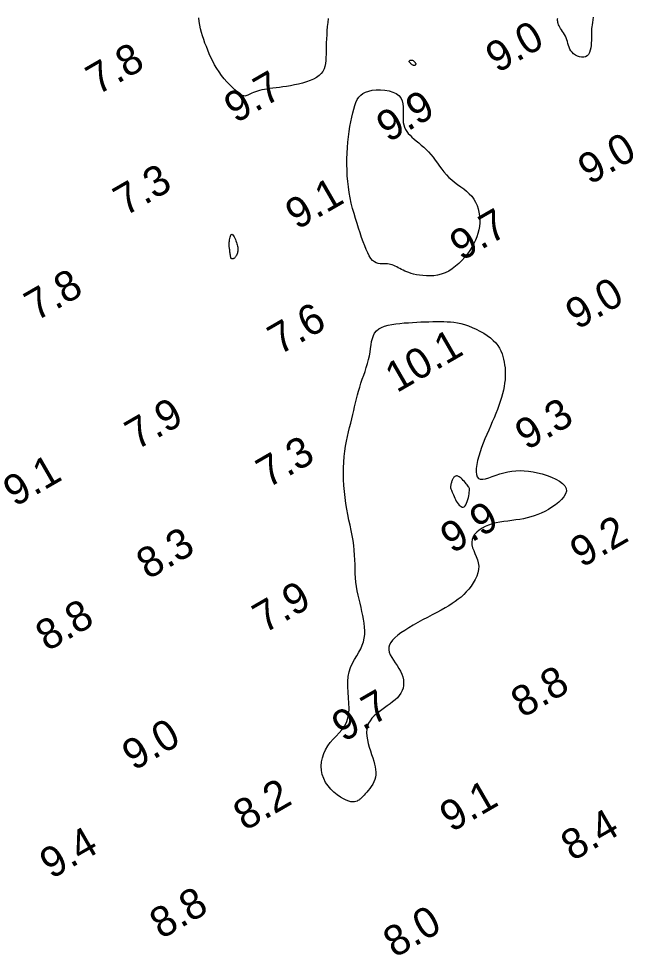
# Model space of a CAD drawing. Extents: x 3024098 to 3056816, y 418252 to 509144.
# Drawn here: x 3036798.1 to 3036899.4, y 419407 to 419561.2 of the extents above; entities that cross this region are included whole.
import ezdxf

# ---------------------------------------------------------------- set-up
doc = ezdxf.new("R2010")
doc.units = 0
doc.layers.add('V-CHAN-CONT-EL10', color=7, linetype='Continuous')
doc.layers.add('V-TOPO-SOUN-0911', color=7, linetype='Continuous')

msp = doc.modelspace()

# ---------------------------------------------------------------- linework, layer by layer
at = {"layer": 'V-CHAN-CONT-EL10'}
for points in [[(3036849.14, 419561.3), (3036849.05, 419560.63), (3036848.98, 419559.95), (3036848.92, 419559.27), (3036848.88, 419558.6), (3036848.84, 419557.93), (3036848.82, 419557.27), (3036848.8, 419556.64), (3036848.78, 419556.02), (3036848.77, 419555.43), (3036848.75, 419554.88), (3036848.72, 419554.35), (3036848.67, 419553.86), (3036848.58, 419553.4), (3036848.44, 419552.97), (3036848.25, 419552.57), (3036847.99, 419552.2), (3036847.65, 419551.87), (3036847.22, 419551.57), (3036846.71, 419551.29), (3036846.15, 419551.05), (3036845.54, 419550.83), (3036844.89, 419550.64), (3036844.23, 419550.47), (3036843.56, 419550.33), (3036842.91, 419550.21), (3036842.28, 419550.1), (3036841.67, 419550.02), (3036841.1, 419549.94), (3036840.55, 419549.87), (3036840.02, 419549.81), (3036839.53, 419549.74), (3036839.06, 419549.67), (3036838.62, 419549.6), (3036838.21, 419549.51), (3036837.82, 419549.41), (3036837.46, 419549.3), (3036837.14, 419549.19), (3036836.83, 419549.08), (3036836.56, 419548.97), (3036836.31, 419548.86), (3036836.1, 419548.75), (3036835.91, 419548.66), (3036835.74, 419548.58), (3036835.58, 419548.53), (3036835.41, 419548.5), (3036835.23, 419548.52), (3036835.02, 419548.6), (3036834.78, 419548.72), (3036834.49, 419548.92), (3036834.15, 419549.18), (3036833.76, 419549.52), (3036833.35, 419549.91), (3036832.9, 419550.36), (3036832.45, 419550.84), (3036832, 419551.36), (3036831.56, 419551.91), (3036831.15, 419552.48), (3036830.77, 419553.07), (3036830.42, 419553.66), (3036830.1, 419554.25), (3036829.81, 419554.85), (3036829.54, 419555.46), (3036829.29, 419556.06), (3036829.06, 419556.65), (3036828.83, 419557.24), (3036828.62, 419557.83), (3036828.43, 419558.4), (3036828.25, 419558.98), (3036828.09, 419559.56), (3036827.96, 419560.16), (3036827.86, 419560.76), (3036827.8, 419561.38)], [(3036892.8, 419561.49), (3036892.72, 419561.05), (3036892.65, 419560.63), (3036892.6, 419560.24), (3036892.55, 419559.91), (3036892.53, 419559.62), (3036892.51, 419559.36), (3036892.5, 419559.11), (3036892.5, 419558.87), (3036892.5, 419558.62), (3036892.5, 419558.34), (3036892.5, 419558.02), (3036892.5, 419557.66), (3036892.48, 419557.26), (3036892.44, 419556.85), (3036892.38, 419556.43), (3036892.3, 419556.04), (3036892.17, 419555.68), (3036892.01, 419555.38), (3036891.79, 419555.14), (3036891.53, 419554.99), (3036891.22, 419554.92), (3036890.89, 419554.92), (3036890.55, 419554.98), (3036890.2, 419555.1), (3036889.88, 419555.26), (3036889.57, 419555.47), (3036889.31, 419555.71), (3036889.1, 419555.97), (3036888.94, 419556.25), (3036888.81, 419556.55), (3036888.71, 419556.85), (3036888.62, 419557.17), (3036888.54, 419557.48), (3036888.45, 419557.79), (3036888.34, 419558.09), (3036888.22, 419558.37), (3036888.07, 419558.65), (3036887.91, 419558.91), (3036887.75, 419559.16), (3036887.59, 419559.4), (3036887.43, 419559.63), (3036887.29, 419559.85), (3036887.18, 419560.05), (3036887.09, 419560.25), (3036887.02, 419560.44), (3036886.97, 419560.62), (3036886.95, 419560.79), (3036886.93, 419560.94), (3036886.93, 419561.08), (3036886.93, 419561.21), (3036886.94, 419561.32)]]:
    msp.add_lwpolyline(points, dxfattribs=at)
for points in [[(3036862.77, 419553.83), (3036862.69, 419553.9), (3036862.63, 419553.97), (3036862.57, 419554.04), (3036862.52, 419554.1), (3036862.49, 419554.17), (3036862.48, 419554.23), (3036862.48, 419554.28), (3036862.51, 419554.33), (3036862.56, 419554.37), (3036862.62, 419554.4), (3036862.7, 419554.42), (3036862.78, 419554.44), (3036862.87, 419554.44), (3036862.96, 419554.43), (3036863.04, 419554.41), (3036863.12, 419554.37), (3036863.19, 419554.33), (3036863.25, 419554.28), (3036863.3, 419554.22), (3036863.35, 419554.17), (3036863.4, 419554.11), (3036863.43, 419554.06), (3036863.46, 419554.02), (3036863.48, 419553.98), (3036863.5, 419553.95), (3036863.51, 419553.92), (3036863.52, 419553.91), (3036863.53, 419553.89), (3036863.54, 419553.88), (3036863.54, 419553.87), (3036863.54, 419553.86), (3036863.55, 419553.85), (3036863.55, 419553.84), (3036863.56, 419553.83), (3036863.56, 419553.82), (3036863.56, 419553.81), (3036863.56, 419553.8), (3036863.56, 419553.79), (3036863.56, 419553.78), (3036863.56, 419553.77), (3036863.56, 419553.76), (3036863.55, 419553.74), (3036863.54, 419553.73), (3036863.53, 419553.72), (3036863.52, 419553.7), (3036863.51, 419553.68), (3036863.5, 419553.66), (3036863.49, 419553.64), (3036863.48, 419553.61), (3036863.46, 419553.59), (3036863.45, 419553.57), (3036863.43, 419553.55), (3036863.4, 419553.53), (3036863.37, 419553.52), (3036863.33, 419553.52), (3036863.29, 419553.53), (3036863.23, 419553.54), (3036863.18, 419553.56), (3036863.12, 419553.59), (3036863.05, 419553.62), (3036862.98, 419553.67), (3036862.91, 419553.72), (3036862.84, 419553.77)], [(3036856.17, 419521.77), (3036855.9, 419522.19), (3036855.64, 419522.68), (3036855.39, 419523.24), (3036855.14, 419523.86), (3036854.89, 419524.52), (3036854.64, 419525.23), (3036854.39, 419525.97), (3036854.14, 419526.73), (3036853.88, 419527.52), (3036853.63, 419528.32), (3036853.39, 419529.15), (3036853.16, 419529.99), (3036852.94, 419530.85), (3036852.75, 419531.73), (3036852.59, 419532.62), (3036852.45, 419533.54), (3036852.35, 419534.46), (3036852.27, 419535.39), (3036852.23, 419536.32), (3036852.2, 419537.26), (3036852.21, 419538.19), (3036852.24, 419539.12), (3036852.29, 419540.03), (3036852.37, 419540.94), (3036852.46, 419541.82), (3036852.58, 419542.68), (3036852.71, 419543.51), (3036852.85, 419544.29), (3036853, 419545.04), (3036853.17, 419545.73), (3036853.34, 419546.37), (3036853.52, 419546.95), (3036853.71, 419547.47), (3036853.93, 419547.92), (3036854.18, 419548.32), (3036854.49, 419548.66), (3036854.85, 419548.94), (3036855.29, 419549.17), (3036855.8, 419549.34), (3036856.4, 419549.46), (3036857.06, 419549.52), (3036857.76, 419549.53), (3036858.47, 419549.47), (3036859.15, 419549.35), (3036859.79, 419549.17), (3036860.34, 419548.92), (3036860.79, 419548.59), (3036861.11, 419548.2), (3036861.32, 419547.74), (3036861.44, 419547.24), (3036861.49, 419546.72), (3036861.49, 419546.17), (3036861.48, 419545.63), (3036861.46, 419545.11), (3036861.46, 419544.61), (3036861.5, 419544.16), (3036861.59, 419543.75), (3036861.71, 419543.37), (3036861.88, 419543.01), (3036862.08, 419542.68), (3036862.33, 419542.36), (3036862.61, 419542.05), (3036862.92, 419541.74), (3036863.27, 419541.43), (3036863.64, 419541.11), (3036864.04, 419540.79), (3036864.45, 419540.44), (3036864.86, 419540.09), (3036865.27, 419539.71), (3036865.67, 419539.31), (3036866.06, 419538.88), (3036866.43, 419538.43), (3036866.78, 419537.96), (3036867.13, 419537.47), (3036867.48, 419536.98), (3036867.83, 419536.49), (3036868.2, 419536.01), (3036868.6, 419535.54), (3036869.02, 419535.11), (3036869.48, 419534.7), (3036869.96, 419534.32), (3036870.46, 419533.95), (3036870.97, 419533.58), (3036871.46, 419533.21), (3036871.94, 419532.83), (3036872.38, 419532.43), (3036872.78, 419532), (3036873.12, 419531.53), (3036873.41, 419531.03), (3036873.65, 419530.5), (3036873.83, 419529.94), (3036873.97, 419529.37), (3036874.06, 419528.79), (3036874.1, 419528.2), (3036874.09, 419527.62), (3036874.04, 419527.04), (3036873.95, 419526.47), (3036873.81, 419525.9), (3036873.63, 419525.33), (3036873.4, 419524.77), (3036873.14, 419524.21), (3036872.82, 419523.65), (3036872.47, 419523.09), (3036872.07, 419522.53), (3036871.64, 419521.98), (3036871.17, 419521.44), (3036870.66, 419520.94), (3036870.13, 419520.47), (3036869.57, 419520.05), (3036868.98, 419519.69), (3036868.38, 419519.4), (3036867.77, 419519.17), (3036867.14, 419519.02), (3036866.51, 419518.93), (3036865.9, 419518.89), (3036865.3, 419518.9), (3036864.72, 419518.94), (3036864.18, 419519.01), (3036863.67, 419519.09), (3036863.21, 419519.2), (3036862.8, 419519.31), (3036862.42, 419519.43), (3036862.08, 419519.56), (3036861.77, 419519.69), (3036861.47, 419519.83), (3036861.2, 419519.97), (3036860.94, 419520.11), (3036860.68, 419520.24), (3036860.43, 419520.37), (3036860.18, 419520.49), (3036859.93, 419520.6), (3036859.68, 419520.7), (3036859.42, 419520.77), (3036859.15, 419520.83), (3036858.88, 419520.86), (3036858.59, 419520.87), (3036858.29, 419520.87), (3036857.98, 419520.86), (3036857.67, 419520.88), (3036857.35, 419520.93), (3036857.05, 419521.03), (3036856.75, 419521.2), (3036856.45, 419521.44)], [(3036832.85, 419524.62), (3036832.88, 419524.83), (3036832.92, 419525.05), (3036832.97, 419525.25), (3036833.02, 419525.44), (3036833.09, 419525.59), (3036833.16, 419525.7), (3036833.24, 419525.74), (3036833.33, 419525.72), (3036833.44, 419525.63), (3036833.54, 419525.49), (3036833.64, 419525.31), (3036833.75, 419525.1), (3036833.85, 419524.87), (3036833.94, 419524.64), (3036834.02, 419524.41), (3036834.09, 419524.19), (3036834.15, 419523.99), (3036834.19, 419523.8), (3036834.22, 419523.62), (3036834.24, 419523.45), (3036834.25, 419523.28), (3036834.25, 419523.12), (3036834.23, 419522.97), (3036834.2, 419522.82), (3036834.17, 419522.67), (3036834.12, 419522.52), (3036834.06, 419522.39), (3036834, 419522.26), (3036833.94, 419522.14), (3036833.88, 419522.04), (3036833.81, 419521.95), (3036833.74, 419521.88), (3036833.67, 419521.82), (3036833.61, 419521.78), (3036833.55, 419521.74), (3036833.49, 419521.72), (3036833.44, 419521.7), (3036833.39, 419521.7), (3036833.34, 419521.69), (3036833.3, 419521.69), (3036833.27, 419521.69), (3036833.24, 419521.7), (3036833.22, 419521.71), (3036833.19, 419521.71), (3036833.18, 419521.73), (3036833.16, 419521.74), (3036833.15, 419521.75), (3036833.14, 419521.77), (3036833.12, 419521.79), (3036833.11, 419521.82), (3036833.1, 419521.86), (3036833.09, 419521.91), (3036833.08, 419521.98), (3036833.06, 419522.07), (3036833.04, 419522.18), (3036833.02, 419522.32), (3036833, 419522.47), (3036832.98, 419522.64), (3036832.95, 419522.82), (3036832.93, 419523), (3036832.91, 419523.17), (3036832.88, 419523.34), (3036832.86, 419523.49), (3036832.84, 419523.61), (3036832.83, 419523.72), (3036832.82, 419523.82), (3036832.81, 419523.92), (3036832.81, 419524.03), (3036832.81, 419524.14), (3036832.82, 419524.28), (3036832.83, 419524.43)], [(3036848.16, 419436.78), (3036848.03, 419437.46), (3036847.99, 419438.16), (3036848.04, 419438.85), (3036848.18, 419439.55), (3036848.39, 419440.22), (3036848.69, 419440.87), (3036849.05, 419441.48), (3036849.47, 419442.05), (3036849.95, 419442.58), (3036850.44, 419443.1), (3036850.93, 419443.62), (3036851.39, 419444.16), (3036851.81, 419444.73), (3036852.15, 419445.35), (3036852.39, 419446.04), (3036852.52, 419446.8), (3036852.56, 419447.63), (3036852.54, 419448.51), (3036852.48, 419449.41), (3036852.41, 419450.33), (3036852.36, 419451.23), (3036852.36, 419452.11), (3036852.43, 419452.93), (3036852.59, 419453.7), (3036852.83, 419454.42), (3036853.14, 419455.09), (3036853.47, 419455.72), (3036853.83, 419456.32), (3036854.17, 419456.9), (3036854.48, 419457.48), (3036854.75, 419458.06), (3036854.94, 419458.64), (3036855.07, 419459.23), (3036855.14, 419459.84), (3036855.15, 419460.45), (3036855.12, 419461.07), (3036855.06, 419461.7), (3036854.96, 419462.34), (3036854.83, 419462.98), (3036854.69, 419463.64), (3036854.54, 419464.3), (3036854.38, 419464.97), (3036854.22, 419465.64), (3036854.07, 419466.33), (3036853.93, 419467.02), (3036853.81, 419467.72), (3036853.71, 419468.43), (3036853.65, 419469.15), (3036853.6, 419469.89), (3036853.57, 419470.63), (3036853.55, 419471.38), (3036853.52, 419472.14), (3036853.48, 419472.92), (3036853.43, 419473.7), (3036853.34, 419474.5), (3036853.23, 419475.3), (3036853.08, 419476.13), (3036852.91, 419476.96), (3036852.73, 419477.82), (3036852.54, 419478.69), (3036852.36, 419479.58), (3036852.19, 419480.49), (3036852.03, 419481.43), (3036851.9, 419482.39), (3036851.79, 419483.36), (3036851.71, 419484.35), (3036851.66, 419485.34), (3036851.64, 419486.32), (3036851.64, 419487.28), (3036851.68, 419488.23), (3036851.75, 419489.14), (3036851.85, 419490.02), (3036851.98, 419490.87), (3036852.14, 419491.68), (3036852.3, 419492.46), (3036852.48, 419493.22), (3036852.66, 419493.95), (3036852.84, 419494.66), (3036853.02, 419495.36), (3036853.18, 419496.04), (3036853.34, 419496.7), (3036853.49, 419497.35), (3036853.64, 419498), (3036853.8, 419498.64), (3036853.96, 419499.28), (3036854.14, 419499.92), (3036854.33, 419500.57), (3036854.53, 419501.21), (3036854.75, 419501.87), (3036854.98, 419502.52), (3036855.2, 419503.17), (3036855.41, 419503.82), (3036855.61, 419504.47), (3036855.78, 419505.1), (3036855.93, 419505.73), (3036856.04, 419506.35), (3036856.12, 419506.95), (3036856.2, 419507.53), (3036856.29, 419508.07), (3036856.41, 419508.59), (3036856.57, 419509.05), (3036856.78, 419509.48), (3036857.07, 419509.84), (3036857.45, 419510.15), (3036857.9, 419510.4), (3036858.42, 419510.61), (3036858.99, 419510.77), (3036859.61, 419510.9), (3036860.27, 419511), (3036860.95, 419511.08), (3036861.64, 419511.14), (3036862.34, 419511.19), (3036863.03, 419511.24), (3036863.72, 419511.27), (3036864.4, 419511.3), (3036865.08, 419511.33), (3036865.73, 419511.34), (3036866.37, 419511.36), (3036866.99, 419511.37), (3036867.58, 419511.37), (3036868.16, 419511.37), (3036868.72, 419511.35), (3036869.28, 419511.31), (3036869.85, 419511.25), (3036870.41, 419511.16), (3036871, 419511.04), (3036871.6, 419510.87), (3036872.23, 419510.66), (3036872.87, 419510.41), (3036873.51, 419510.12), (3036874.14, 419509.8), (3036874.75, 419509.45), (3036875.33, 419509.08), (3036875.86, 419508.68), (3036876.33, 419508.27), (3036876.73, 419507.85), (3036877.07, 419507.42), (3036877.35, 419506.98), (3036877.58, 419506.53), (3036877.77, 419506.08), (3036877.92, 419505.62), (3036878.03, 419505.16), (3036878.13, 419504.69), (3036878.2, 419504.23), (3036878.26, 419503.76), (3036878.29, 419503.28), (3036878.31, 419502.79), (3036878.29, 419502.29), (3036878.26, 419501.78), (3036878.2, 419501.24), (3036878.11, 419500.68), (3036877.99, 419500.1), (3036877.84, 419499.49), (3036877.66, 419498.87), (3036877.46, 419498.23), (3036877.24, 419497.57), (3036877, 419496.9), (3036876.74, 419496.22), (3036876.46, 419495.54), (3036876.17, 419494.85), (3036875.87, 419494.16), (3036875.57, 419493.46), (3036875.26, 419492.76), (3036874.96, 419492.06), (3036874.68, 419491.35), (3036874.4, 419490.64), (3036874.16, 419489.92), (3036873.94, 419489.2), (3036873.75, 419488.49), (3036873.61, 419487.82), (3036873.52, 419487.19), (3036873.5, 419486.63), (3036873.54, 419486.16), (3036873.67, 419485.78), (3036873.88, 419485.53), (3036874.19, 419485.4), (3036874.59, 419485.39), (3036875.05, 419485.48), (3036875.58, 419485.63), (3036876.16, 419485.83), (3036876.78, 419486.05), (3036877.42, 419486.27), (3036878.07, 419486.47), (3036878.73, 419486.62), (3036879.39, 419486.73), (3036880.06, 419486.8), (3036880.74, 419486.82), (3036881.44, 419486.8), (3036882.15, 419486.73), (3036882.88, 419486.62), (3036883.64, 419486.46), (3036884.41, 419486.27), (3036885.19, 419486.03), (3036885.94, 419485.75), (3036886.63, 419485.44), (3036887.25, 419485.09), (3036887.75, 419484.72), (3036888.13, 419484.32), (3036888.34, 419483.89), (3036888.37, 419483.45), (3036888.24, 419482.99), (3036887.97, 419482.53), (3036887.58, 419482.07), (3036887.11, 419481.63), (3036886.57, 419481.2), (3036886, 419480.8), (3036885.4, 419480.43), (3036884.82, 419480.11), (3036884.24, 419479.83), (3036883.67, 419479.58), (3036883.09, 419479.37), (3036882.51, 419479.19), (3036881.92, 419479.04), (3036881.32, 419478.9), (3036880.7, 419478.79), (3036880.06, 419478.7), (3036879.4, 419478.61), (3036878.74, 419478.52), (3036878.08, 419478.43), (3036877.43, 419478.33), (3036876.79, 419478.2), (3036876.16, 419478.04), (3036875.56, 419477.85), (3036875, 419477.61), (3036874.48, 419477.33), (3036874, 419477.02), (3036873.6, 419476.67), (3036873.26, 419476.3), (3036873, 419475.9), (3036872.83, 419475.48), (3036872.77, 419475.04), (3036872.8, 419474.59), (3036872.92, 419474.13), (3036873.1, 419473.66), (3036873.31, 419473.17), (3036873.52, 419472.67), (3036873.72, 419472.16), (3036873.86, 419471.63), (3036873.93, 419471.09), (3036873.91, 419470.54), (3036873.79, 419469.98), (3036873.6, 419469.42), (3036873.35, 419468.87), (3036873.04, 419468.33), (3036872.68, 419467.81), (3036872.29, 419467.31), (3036871.88, 419466.84), (3036871.46, 419466.41), (3036871.02, 419466.01), (3036870.56, 419465.64), (3036870.07, 419465.28), (3036869.55, 419464.93), (3036868.99, 419464.58), (3036868.38, 419464.22), (3036867.72, 419463.86), (3036867.01, 419463.47), (3036866.25, 419463.07), (3036865.47, 419462.65), (3036864.68, 419462.23), (3036863.9, 419461.8), (3036863.13, 419461.37), (3036862.4, 419460.94), (3036861.73, 419460.52), (3036861.12, 419460.11), (3036860.58, 419459.71), (3036860.11, 419459.31), (3036859.73, 419458.92), (3036859.43, 419458.52), (3036859.23, 419458.12), (3036859.11, 419457.73), (3036859.1, 419457.32), (3036859.19, 419456.91), (3036859.36, 419456.48), (3036859.59, 419456.05), (3036859.87, 419455.61), (3036860.17, 419455.17), (3036860.48, 419454.72), (3036860.78, 419454.26), (3036861.04, 419453.79), (3036861.25, 419453.32), (3036861.41, 419452.85), (3036861.51, 419452.38), (3036861.56, 419451.92), (3036861.54, 419451.46), (3036861.46, 419451.02), (3036861.32, 419450.59), (3036861.12, 419450.18), (3036860.85, 419449.8), (3036860.53, 419449.43), (3036860.16, 419449.09), (3036859.75, 419448.75), (3036859.32, 419448.42), (3036858.87, 419448.1), (3036858.41, 419447.78), (3036857.96, 419447.45), (3036857.51, 419447.12), (3036857.09, 419446.78), (3036856.7, 419446.42), (3036856.34, 419446.04), (3036856.04, 419445.64), (3036855.79, 419445.21), (3036855.6, 419444.74), (3036855.49, 419444.23), (3036855.46, 419443.69), (3036855.49, 419443.1), (3036855.59, 419442.5), (3036855.73, 419441.89), (3036855.9, 419441.27), (3036856.09, 419440.66), (3036856.28, 419440.06), (3036856.46, 419439.5), (3036856.63, 419438.97), (3036856.77, 419438.48), (3036856.87, 419438.02), (3036856.95, 419437.58), (3036856.98, 419437.16), (3036856.98, 419436.75), (3036856.92, 419436.36), (3036856.82, 419435.97), (3036856.66, 419435.58), (3036856.46, 419435.2), (3036856.23, 419434.83), (3036855.98, 419434.48), (3036855.72, 419434.16), (3036855.47, 419433.86), (3036855.24, 419433.59), (3036855.03, 419433.37), (3036854.86, 419433.18), (3036854.73, 419433.04), (3036854.62, 419432.93), (3036854.53, 419432.84), (3036854.44, 419432.76), (3036854.36, 419432.7), (3036854.27, 419432.63), (3036854.16, 419432.56), (3036854.04, 419432.48), (3036853.88, 419432.4), (3036853.69, 419432.33), (3036853.46, 419432.28), (3036853.2, 419432.27), (3036852.88, 419432.3), (3036852.52, 419432.38), (3036852.11, 419432.54), (3036851.64, 419432.77), (3036851.13, 419433.07), (3036850.6, 419433.44), (3036850.08, 419433.87), (3036849.58, 419434.36), (3036849.11, 419434.9), (3036848.71, 419435.49), (3036848.39, 419436.12)], [(3036871.82, 419481.19), (3036871.94, 419481.44), (3036872.05, 419481.73), (3036872.14, 419482.05), (3036872.22, 419482.38), (3036872.28, 419482.7), (3036872.34, 419483), (3036872.38, 419483.26), (3036872.41, 419483.47), (3036872.43, 419483.64), (3036872.43, 419483.77), (3036872.41, 419483.88), (3036872.38, 419483.98), (3036872.32, 419484.08), (3036872.25, 419484.18), (3036872.15, 419484.31), (3036872.03, 419484.46), (3036871.88, 419484.64), (3036871.73, 419484.83), (3036871.56, 419485.02), (3036871.38, 419485.22), (3036871.21, 419485.4), (3036871.04, 419485.56), (3036870.88, 419485.7), (3036870.73, 419485.81), (3036870.6, 419485.88), (3036870.47, 419485.93), (3036870.36, 419485.95), (3036870.26, 419485.95), (3036870.16, 419485.93), (3036870.08, 419485.9), (3036870, 419485.85), (3036869.92, 419485.79), (3036869.85, 419485.72), (3036869.78, 419485.64), (3036869.72, 419485.55), (3036869.66, 419485.45), (3036869.6, 419485.35), (3036869.55, 419485.23), (3036869.51, 419485.11), (3036869.46, 419484.99), (3036869.42, 419484.86), (3036869.39, 419484.73), (3036869.35, 419484.6), (3036869.33, 419484.47), (3036869.31, 419484.36), (3036869.29, 419484.25), (3036869.28, 419484.16), (3036869.28, 419484.09), (3036869.29, 419484.02), (3036869.3, 419483.96), (3036869.32, 419483.9), (3036869.35, 419483.82), (3036869.39, 419483.73), (3036869.44, 419483.61), (3036869.5, 419483.46), (3036869.58, 419483.28), (3036869.66, 419483.06), (3036869.75, 419482.82), (3036869.86, 419482.57), (3036869.98, 419482.31), (3036870.1, 419482.05), (3036870.24, 419481.79), (3036870.39, 419481.56), (3036870.55, 419481.34), (3036870.71, 419481.15), (3036870.88, 419481), (3036871.06, 419480.89), (3036871.22, 419480.83), (3036871.39, 419480.82), (3036871.55, 419480.88), (3036871.69, 419481)]]:
    msp.add_lwpolyline(points, close=True, dxfattribs=at)

# ---------------------------------------------------------------- texts
at = {"layer": 'V-TOPO-SOUN-0911'}
for s, p in [('9.0', (3036877, 419552.21)), ('7.8', (3036811.14, 419548.6)), ('9.7', (3036833.9, 419543.94)), ('9.9', (3036859, 419540.79)), ('9.0', (3036892.19, 419533.8)), ('7.3', (3036815.66, 419528.65)), ('9.1', (3036843.99, 419526.41)), ('9.7', (3036871.08, 419521.27)), ('7.8', (3036801, 419511.36)), ('9.0', (3036890.15, 419509.95)), ('7.6', (3036841.09, 419505.79)), ('10.1 ', (3036860.43, 419499.56)), ('7.9', (3036817.57, 419490.14)), ('9.3', (3036881.84, 419490.1)), ('7.3', (3036839.19, 419483.87)), ('9.1', (3036797.5, 419480.77)), ('9.9', (3036869.53, 419473.08)), ('9.2', (3036890.89, 419470.75)), ('8.3', (3036819.44, 419468.81)), ('7.9', (3036838.6, 419459.95)), ('8.8', (3036802.83, 419456.97)), ('8.8', (3036881.15, 419446.01)), ('9.7', (3036851.65, 419442.04)), ('9.0', (3036817.09, 419437.31)), ('8.2', (3036835.41, 419427.41)), ('9.1', (3036869.42, 419427.19)), ('8.4', (3036889.38, 419422.42)), ('9.4', (3036803.52, 419419.47)), ('8.8', (3036821.63, 419409.59)), ('8.0', (3036860.1, 419406.51))]:
    msp.add_text(s, height=5, rotation=30, dxfattribs=at).set_placement(p)

doc.saveas('drawing.dxf')
